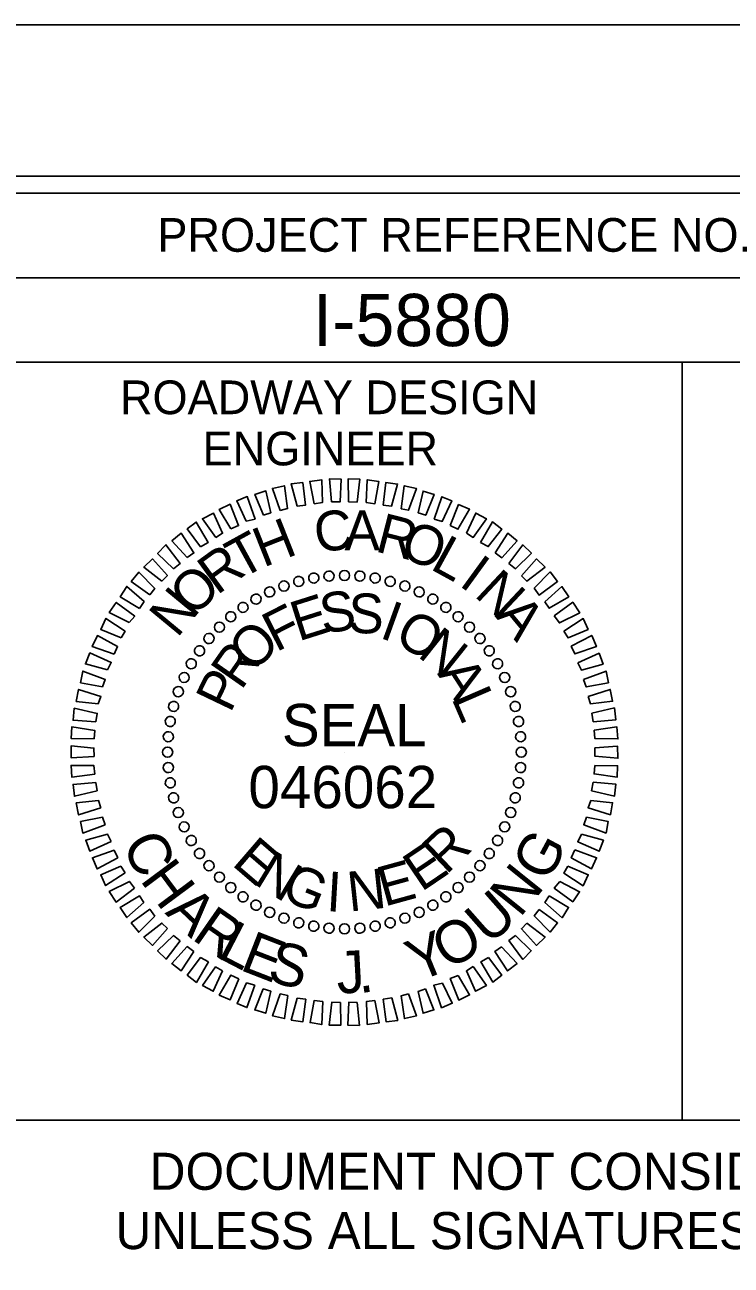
# Model space of a CAD drawing. Extents: x 1648649 to 1651827, y 844691 to 845879.
# Drawn here: x 1651431.8 to 1651536.5, y 845606.9 to 845791 of the extents above; entities that cross this region are included whole.
import ezdxf

# ---------------------------------------------------------------- set-up
doc = ezdxf.new("R2010")
doc.units = 0
for name, color, linetype in [('Default', 7, 'Continuous'), ('Old_Level_2', 7, 'Continuous'), ('Sheet Cutting Line CELL', 7, 'Continuous'), ('Sheet Data Field CELL', 7, 'Continuous'), ('Sheet Plot Border Inside CELL', 7, 'Continuous'), ('Sheet Plot Border Outside CELL', 7, 'Continuous'), ('Sheet Profile CELL', 7, 'Continuous'), ('Sheet Profile Grid Major CELL', 7, 'Continuous'), ('Sheet Profile Grid Minor CELL', 7, 'Continuous'), ('Sheet Sticker Exception Certification CELL', 7, 'Continuous')]:
    doc.layers.add(name, color=color, linetype=linetype)

msp = doc.modelspace()

# ---------------------------------------------------------------- linework, layer by layer
at = {"layer": 'Old_Level_2'}
for p, q in [((1651472.36, 845708.44), (1651472.36, 845708.44)), ((1651474.65, 845708.89), (1651474.65, 845708.89)), ((1651476.9, 845709.25), (1651476.9, 845709.25)), ((1651479.2, 845709.34), (1651479.2, 845709.34)), ((1651481.5, 845709.22), (1651481.5, 845709.22)), ((1651483.75, 845708.9), (1651483.75, 845708.9)), ((1651485.96, 845708.46), (1651485.96, 845708.46)), ((1651468.1, 845706.9), (1651468.1, 845706.9)), ((1651470.18, 845707.77), (1651470.18, 845707.77)), ((1651488.17, 845707.77), (1651488.17, 845707.77)), ((1651490.27, 845706.87), (1651490.27, 845706.87)), ((1651464.11, 845704.58), (1651464.11, 845704.58)), ((1651466.08, 845705.82), (1651466.08, 845705.82)), ((1651492.33, 845705.86), (1651492.33, 845705.86)), ((1651494.24, 845704.58), (1651494.24, 845704.58)), ((1651462.31, 845703.24), (1651462.31, 845703.24)), ((1651496.09, 845703.2), (1651496.09, 845703.2)), ((1651460.61, 845701.64), (1651460.61, 845701.64)), ((1651497.74, 845701.66), (1651497.74, 845701.66)), ((1651459.07, 845699.99), (1651459.07, 845699.99)), ((1651499.34, 845699.96), (1651499.34, 845699.96)), ((1651457.69, 845698.14), (1651457.69, 845698.14)), ((1651500.68, 845698.16), (1651500.68, 845698.16)), ((1651456.42, 845696.23), (1651456.42, 845696.23)), ((1651501.91, 845696.19), (1651501.91, 845696.19)), ((1651455.41, 845694.18), (1651455.41, 845694.18)), ((1651502.99, 845694.17), (1651502.99, 845694.17)), ((1651454.5, 845692.07), (1651454.5, 845692.07)), ((1651503.87, 845692.09), (1651503.87, 845692.09)), ((1651453.81, 845689.86), (1651453.81, 845689.86)), ((1651504.53, 845689.91), (1651504.53, 845689.91)), ((1651453.37, 845687.66), (1651453.37, 845687.66)), ((1651504.99, 845687.62), (1651504.99, 845687.62)), ((1651453.05, 845685.4), (1651453.05, 845685.4)), ((1651505.34, 845685.37), (1651505.34, 845685.37)), ((1651452.93, 845683.1), (1651452.93, 845683.1)), ((1651479.18, 845683.09), (1651479.18, 845683.09)), ((1651505.44, 845683.07), (1651505.44, 845683.07)), ((1651453.02, 845680.8), (1651453.02, 845680.8)), ((1651505.32, 845680.77), (1651505.32, 845680.77)), ((1651453.38, 845678.56), (1651453.38, 845678.56)), ((1651504.99, 845678.52), (1651504.99, 845678.52)), ((1651453.84, 845676.26), (1651453.84, 845676.26)), ((1651504.56, 845676.31), (1651504.56, 845676.31)), ((1651454.5, 845674.08), (1651454.5, 845674.08)), ((1651503.87, 845674.1), (1651503.87, 845674.1)), ((1651455.37, 845672), (1651455.37, 845672)), ((1651502.96, 845672), (1651502.96, 845672)), ((1651456.46, 845669.98), (1651456.46, 845669.98)), ((1651501.95, 845669.94), (1651501.95, 845669.94)), ((1651457.69, 845668.02), (1651457.69, 845668.02)), ((1651500.68, 845668.03), (1651500.68, 845668.03)), ((1651459.03, 845666.21), (1651459.03, 845666.21)), ((1651499.3, 845666.18), (1651499.3, 845666.18)), ((1651460.63, 845664.51), (1651460.63, 845664.51)), ((1651497.76, 845664.53), (1651497.76, 845664.53)), ((1651462.28, 845662.97), (1651462.28, 845662.97)), ((1651496.06, 845662.93), (1651496.06, 845662.93)), ((1651464.13, 845661.59), (1651464.13, 845661.59)), ((1651466.04, 845660.32), (1651466.04, 845660.32)), ((1651492.29, 845660.36), (1651492.29, 845660.36)), ((1651494.25, 845661.59), (1651494.25, 845661.59)), ((1651468.09, 845659.31), (1651468.09, 845659.31)), ((1651490.27, 845659.28), (1651490.27, 845659.28)), ((1651470.2, 845658.4), (1651470.2, 845658.4)), ((1651472.41, 845657.71), (1651472.41, 845657.71)), ((1651474.61, 845657.28), (1651474.61, 845657.28)), ((1651476.87, 845656.95), (1651476.87, 845656.95)), ((1651479.17, 845656.83), (1651479.17, 845656.83)), ((1651481.47, 845656.93), (1651481.47, 845656.93)), ((1651483.71, 845657.28), (1651483.71, 845657.28)), ((1651486.01, 845657.74), (1651486.01, 845657.74)), ((1651488.19, 845658.4), (1651488.19, 845658.4))]:
    msp.add_line(p, q, dxfattribs=at)
for points in [[(1651472.17, 845719.57), (1651471.27, 845722.9), (1651473, 845723.09), (1651473.42, 845719.75)], [(1651474.67, 845719.93), (1651474.04, 845723.26), (1651475.81, 845723.5), (1651475.92, 845720.11)], [(1651477.28, 845720.24), (1651476.96, 845723.63), (1651478.69, 845723.61), (1651478.54, 845720.21)], [(1651479.79, 845720.23), (1651479.73, 845723.63), (1651481.46, 845723.6), (1651481.05, 845720.2)], [(1651482.41, 845720.12), (1651482.56, 845723.52), (1651484.29, 845723.23), (1651483.67, 845719.93)], [(1651484.92, 845719.74), (1651485.34, 845723.1), (1651487.07, 845722.86), (1651486.18, 845719.61)], [(1651467.17, 845718.23), (1651465.91, 845721.34), (1651467.53, 845721.84), (1651468.26, 845718.61)], [(1651469.67, 845718.95), (1651468.51, 845722.23), (1651470.28, 845722.62), (1651470.76, 845719.23)], [(1651487.6, 845719.21), (1651488.06, 845722.62), (1651489.85, 845722.23), (1651488.7, 845718.97)], [(1651490.12, 845718.58), (1651490.85, 845721.83), (1651492.48, 845721.34), (1651491.23, 845718.23)], [(1651462.34, 845716.21), (1651460.62, 845719.11), (1651462.23, 845719.87), (1651463.48, 845716.7)], [(1651464.62, 845717.35), (1651463.21, 845720.36), (1651464.77, 845721.01), (1651465.92, 845717.68)], [(1651492.49, 845717.68), (1651493.64, 845720.99), (1651495.11, 845720.39), (1651493.7, 845717.33)], [(1651494.86, 845716.72), (1651496.11, 845719.83), (1651497.75, 845719.13), (1651496.02, 845716.17)], [(1651460.12, 845714.92), (1651458.13, 845717.71), (1651459.74, 845718.57), (1651461.1, 845715.56)], [(1651497.29, 845715.56), (1651498.65, 845718.57), (1651500.23, 845717.71), (1651498.29, 845714.95)], [(1651455.88, 845711.97), (1651453.59, 845714.44), (1651454.98, 845715.56), (1651456.86, 845712.66)], [(1651457.84, 845713.57), (1651455.86, 845716.2), (1651457.2, 845717.22), (1651458.98, 845714.22)], [(1651499.35, 845714.19), (1651501.13, 845717.25), (1651502.51, 845716.18), (1651500.51, 845713.58)], [(1651501.52, 845712.66), (1651503.41, 845715.57), (1651504.79, 845714.44), (1651502.53, 845711.94)], [(1651453.82, 845710.31), (1651451.48, 845712.57), (1651452.71, 845713.85), (1651454.8, 845711.06)], [(1651503.54, 845711.07), (1651505.63, 845713.83), (1651506.91, 845712.59), (1651504.54, 845710.3)], [(1651452.12, 845708.45), (1651449.42, 845710.55), (1651450.71, 845711.77), (1651452.94, 845709.3)], [(1651505.45, 845709.27), (1651507.66, 845711.77), (1651508.93, 845710.54), (1651506.25, 845708.45)], [(1651450.33, 845706.43), (1651447.57, 845708.42), (1651448.7, 845709.8), (1651451.04, 845707.38)], [(1651507.31, 845707.42), (1651509.68, 845709.82), (1651510.8, 845708.43), (1651508.06, 845706.39)], [(1651448.79, 845704.42), (1651445.94, 845706.14), (1651446.91, 845707.68), (1651449.46, 845705.42)], [(1651508.92, 845705.41), (1651511.44, 845707.65), (1651512.46, 845706.15), (1651509.56, 845704.43)], [(1651447.26, 845702.3), (1651444.31, 845703.81), (1651445.33, 845705.3), (1651448.08, 845703.25)], [(1651510.31, 845703.29), (1651513.05, 845705.33), (1651514.07, 845703.78), (1651511.06, 845702.26)], [(1651446.05, 845700.03), (1651443.04, 845701.28), (1651443.8, 845702.92), (1651446.66, 845701.03)], [(1651511.71, 845701.02), (1651514.61, 845702.9), (1651515.32, 845701.29), (1651512.36, 845700.03)], [(1651445.04, 845697.6), (1651441.78, 845698.75), (1651442.54, 845700.38), (1651445.55, 845698.76)], [(1651512.8, 845698.79), (1651515.86, 845700.41), (1651516.56, 845698.75), (1651513.34, 845697.65)], [(1651444.04, 845695.29), (1651440.78, 845696.17), (1651441.43, 845697.8), (1651444.59, 845696.39)], [(1651513.78, 845696.35), (1651516.95, 845697.76), (1651517.55, 845696.15), (1651514.32, 845695.26)], [(1651443.3, 845692.76), (1651440.04, 845693.39), (1651440.38, 845695.12), (1651443.7, 845693.87)], [(1651514.66, 845693.85), (1651517.99, 845695.11), (1651518.33, 845693.39), (1651515.05, 845692.76)], [(1651442.66, 845690.24), (1651439.41, 845690.6), (1651439.75, 845692.39), (1651443.06, 845691.35)], [(1651515.33, 845691.35), (1651518.61, 845692.4), (1651518.95, 845690.63), (1651515.67, 845690.26)], [(1651442.29, 845687.57), (1651438.94, 845687.82), (1651439.12, 845689.6), (1651442.53, 845688.83)], [(1651515.85, 845688.85), (1651519.23, 845689.64), (1651519.42, 845687.87), (1651516.08, 845687.6)], [(1651442.07, 845685.05), (1651438.67, 845685.1), (1651438.75, 845686.83), (1651442.15, 845686.31)], [(1651516.21, 845686.35), (1651519.6, 845686.82), (1651519.73, 845685.05), (1651516.33, 845685.09)], [(1651442.07, 845682.44), (1651438.67, 845682.22), (1651438.64, 845684), (1651442.04, 845683.69)], [(1651516.3, 845683.73), (1651519.7, 845683.95), (1651519.73, 845682.17), (1651516.33, 845682.48)], [(1651442.16, 845679.83), (1651438.77, 845679.35), (1651438.64, 845681.12), (1651442.04, 845681.08)], [(1651516.3, 845681.12), (1651519.7, 845681.07), (1651519.62, 845679.35), (1651516.21, 845679.86)], [(1651442.52, 845677.32), (1651439.14, 845676.53), (1651438.95, 845678.3), (1651442.29, 845678.57)], [(1651516.08, 845678.61), (1651519.43, 845678.35), (1651519.25, 845676.57), (1651515.84, 845677.35)], [(1651443.04, 845674.82), (1651439.76, 845673.77), (1651439.41, 845675.54), (1651442.7, 845675.91)], [(1651515.71, 845675.93), (1651518.96, 845675.57), (1651518.62, 845673.79), (1651515.31, 845674.83)], [(1651443.71, 845672.32), (1651440.38, 845671.06), (1651440.04, 845672.78), (1651443.32, 845673.41)], [(1651515.07, 845673.41), (1651518.32, 845672.79), (1651517.99, 845671.06), (1651514.67, 845672.31)], [(1651444.59, 845669.83), (1651441.42, 845668.41), (1651440.82, 845670.02), (1651444.04, 845670.92)], [(1651514.33, 845670.89), (1651517.59, 845670), (1651516.94, 845668.37), (1651513.78, 845669.78)], [(1651445.57, 845667.39), (1651442.51, 845665.76), (1651441.8, 845667.42), (1651445.03, 845668.53)], [(1651513.33, 845668.57), (1651516.59, 845667.42), (1651515.83, 845665.79), (1651512.82, 845667.41)], [(1651446.66, 845665.16), (1651443.76, 845663.28), (1651443.05, 845664.88), (1651446.01, 845666.14)], [(1651512.32, 845666.15), (1651515.33, 845664.89), (1651514.57, 845663.26), (1651511.71, 845665.14)], [(1651448.05, 845662.88), (1651445.32, 845660.84), (1651444.3, 845662.4), (1651447.3, 845663.91)], [(1651511.11, 845663.88), (1651514.06, 845662.36), (1651513.04, 845660.88), (1651510.29, 845662.92)], [(1651449.45, 845660.76), (1651446.93, 845658.52), (1651445.91, 845660.02), (1651448.81, 845661.74)], [(1651509.57, 845661.76), (1651512.43, 845660.03), (1651511.46, 845658.5), (1651508.91, 845660.75)], [(1651451.06, 845658.75), (1651448.69, 845656.35), (1651447.57, 845657.75), (1651450.31, 845659.78)], [(1651508.04, 845659.74), (1651510.8, 845657.75), (1651509.67, 845656.37), (1651507.33, 845658.79)], [(1651452.92, 845656.9), (1651450.71, 845654.4), (1651449.44, 845655.63), (1651452.12, 845657.72)], [(1651506.25, 845657.72), (1651508.95, 845655.63), (1651507.66, 845654.4), (1651505.42, 845656.87)], [(1651454.83, 845655.1), (1651452.74, 845652.35), (1651451.46, 845653.58), (1651453.83, 845655.87)], [(1651504.55, 845655.86), (1651506.89, 845653.6), (1651505.66, 845652.33), (1651503.57, 845655.12)], [(1651456.85, 845653.52), (1651454.96, 845650.61), (1651453.58, 845651.73), (1651455.84, 845654.23)], [(1651502.49, 845654.21), (1651504.78, 845651.74), (1651503.39, 845650.61), (1651501.51, 845653.51)], [(1651459.02, 845651.98), (1651457.24, 845648.92), (1651455.86, 845649.99), (1651457.86, 845652.59)], [(1651461.08, 845650.61), (1651459.72, 845647.6), (1651458.14, 845648.46), (1651460.08, 845651.22)], [(1651498.25, 845651.26), (1651500.24, 845648.47), (1651498.63, 845647.6), (1651497.27, 845650.61)], [(1651500.53, 845652.6), (1651502.51, 845649.97), (1651501.17, 845648.95), (1651499.39, 845651.96)], [(1651463.51, 845649.45), (1651462.25, 845646.34), (1651460.62, 845647.04), (1651462.35, 845650)], [(1651496.03, 845649.96), (1651497.75, 845647.06), (1651496.14, 845646.3), (1651494.88, 845649.47)], [(1651465.88, 845648.5), (1651464.73, 845645.18), (1651463.26, 845645.78), (1651464.67, 845648.84)], [(1651468.25, 845647.6), (1651467.52, 845644.34), (1651465.89, 845644.83), (1651467.14, 845647.94)], [(1651491.2, 845647.94), (1651492.46, 845644.83), (1651490.84, 845644.33), (1651490.11, 845647.56)], [(1651493.75, 845648.82), (1651495.16, 845645.82), (1651493.6, 845645.16), (1651492.44, 845648.49)], [(1651470.77, 845646.96), (1651470.3, 845643.55), (1651468.52, 845643.94), (1651469.67, 845647.2)], [(1651473.44, 845646.43), (1651473.03, 845643.08), (1651471.3, 845643.31), (1651472.19, 845646.57)], [(1651475.96, 845646.06), (1651475.81, 845642.65), (1651474.08, 845642.94), (1651474.7, 845646.24)], [(1651478.58, 845645.95), (1651478.64, 845642.55), (1651476.91, 845642.57), (1651477.32, 845645.98)], [(1651481.09, 845645.94), (1651481.41, 845642.54), (1651479.68, 845642.57), (1651479.83, 845645.97)], [(1651483.7, 845646.24), (1651484.33, 845642.91), (1651482.56, 845642.67), (1651482.45, 845646.07)], [(1651486.2, 845646.6), (1651487.1, 845643.27), (1651485.37, 845643.08), (1651484.95, 845646.42)], [(1651488.7, 845647.22), (1651489.86, 845643.95), (1651488.09, 845643.55), (1651487.61, 845646.94)]]:
    msp.add_lwpolyline(points, close=True, dxfattribs=at)
for centre, major_axis in [((1651476.9, 845709.21), (-0.066, 0.75)), ((1651479.18, 845709.31), (0, 0.753)), ((1651481.47, 845709.21), (0.066, 0.75)), ((1651470.21, 845707.73), (-0.258, 0.708)), ((1651472.4, 845708.42), (-0.195, 0.727)), ((1651474.63, 845708.92), (-0.131, 0.742)), ((1651483.74, 845708.92), (0.131, 0.742)), ((1651485.97, 845708.42), (0.195, 0.727)), ((1651488.15, 845707.73), (0.258, 0.708)), ((1651466.07, 845705.8), (-0.376, 0.652)), ((1651468.1, 845706.86), (-0.318, 0.682)), ((1651490.27, 845706.86), (0.318, 0.682)), ((1651492.3, 845705.8), (0.376, 0.652)), ((1651464.14, 845704.57), (-0.432, 0.617)), ((1651494.23, 845704.57), (0.432, 0.617)), ((1651462.33, 845703.18), (-0.484, 0.577)), ((1651496.04, 845703.18), (0.484, 0.577)), ((1651459.09, 845699.95), (-0.577, 0.484)), ((1651460.64, 845701.63), (-0.532, 0.532)), ((1651497.73, 845701.63), (0.532, 0.532)), ((1651499.28, 845699.95), (0.577, 0.484)), ((1651457.7, 845698.13), (-0.617, 0.432)), ((1651500.67, 845698.13), (0.617, 0.432)), ((1651456.47, 845696.2), (-0.652, 0.376)), ((1651501.9, 845696.2), (0.652, 0.376)), ((1651455.41, 845694.17), (-0.682, 0.318)), ((1651502.95, 845694.17), (0.682, 0.318)), ((1651454.54, 845692.06), (-0.708, 0.258)), ((1651503.83, 845692.06), (0.708, 0.258)), ((1651453.85, 845689.87), (-0.727, 0.195)), ((1651504.52, 845689.87), (0.727, 0.195)), ((1651453.36, 845687.64), (-0.742, 0.131)), ((1651505.01, 845687.64), (0.742, 0.131)), ((1651453.06, 845685.37), (-0.75, 0.066)), ((1651505.31, 845685.37), (0.75, 0.066)), ((1651452.96, 845683.09), (-0.753, 0)), ((1651505.41, 845683.09), (0.753, 0)), ((1651453.06, 845680.8), (-0.75, -0.066)), ((1651505.31, 845680.8), (0.75, -0.066)), ((1651453.36, 845678.53), (-0.742, -0.131)), ((1651505.01, 845678.53), (0.742, -0.131)), ((1651453.85, 845676.3), (-0.727, -0.195)), ((1651504.52, 845676.3), (0.727, -0.195)), ((1651454.54, 845674.12), (-0.708, -0.258)), ((1651503.83, 845674.12), (0.708, -0.258)), ((1651455.41, 845672), (-0.682, -0.318)), ((1651502.95, 845672), (0.682, -0.318)), ((1651456.47, 845669.97), (-0.652, -0.376)), ((1651501.9, 845669.97), (0.652, -0.376)), ((1651457.7, 845668.04), (-0.617, -0.432)), ((1651500.67, 845668.04), (0.617, -0.432)), ((1651459.09, 845666.23), (-0.577, -0.484)), ((1651499.28, 845666.23), (0.577, -0.484)), ((1651460.64, 845664.54), (-0.532, -0.532)), ((1651497.73, 845664.54), (0.532, -0.532)), ((1651462.33, 845662.99), (-0.484, -0.577)), ((1651464.14, 845661.6), (-0.432, -0.617)), ((1651494.23, 845661.6), (0.432, -0.617)), ((1651496.04, 845662.99), (0.484, -0.577)), ((1651466.07, 845660.37), (-0.376, -0.652)), ((1651492.3, 845660.37), (0.376, -0.652)), ((1651468.1, 845659.32), (-0.318, -0.682)), ((1651470.21, 845658.44), (-0.258, -0.708)), ((1651472.4, 845657.75), (-0.195, -0.727)), ((1651485.97, 845657.75), (0.195, -0.727)), ((1651488.15, 845658.44), (0.258, -0.708)), ((1651490.27, 845659.32), (0.318, -0.682)), ((1651474.63, 845657.26), (-0.131, -0.742)), ((1651476.9, 845656.96), (-0.066, -0.75)), ((1651479.18, 845656.86), (0, -0.753)), ((1651481.47, 845656.96), (0.066, -0.75)), ((1651483.74, 845657.26), (0.131, -0.742))]:
    msp.add_ellipse(centre, major_axis=major_axis, ratio=0.999708, dxfattribs=at)
at = {"layer": 'Sheet Cutting Line CELL'}
msp.add_line((1651646.28, 845791.02), (1649962.28, 845791.02), dxfattribs=at)
at = {"layer": 'Sheet Plot Border Inside CELL'}
msp.add_lwpolyline([(1649975.28, 844713.47), (1651641.78, 844713.47), (1651641.78, 845768.57), (1649975.28, 845768.57)], close=True, dxfattribs=at)
at = {"layer": 'Sheet Plot Border Outside CELL'}
msp.add_lwpolyline([(1649962.28, 844691.02), (1651646.28, 844691.02), (1651646.28, 845791.02), (1649962.28, 845791.02)], close=True, dxfattribs=at)
at = {"layer": 'Sheet Profile CELL'}
for p, q in [((1651429.23, 845753.47), (1651629.28, 845753.47)), ((1651529.28, 845740.97), (1651529.28, 845628.52))]:
    msp.add_line(p, q, dxfattribs=at)
for points in [[(1651629.28, 845766.02), (1650129.28, 845766.02), (1650129.28, 844716.02), (1651629.28, 844716.02)], [(1651429.23, 845766.02), (1651629.28, 845766.02), (1651629.28, 845740.97), (1651429.23, 845740.97)], [(1651429.23, 845740.97), (1651529.28, 845740.97), (1651529.28, 845628.47), (1651429.23, 845628.47)], [(1651529.28, 845740.97), (1651629.28, 845740.97), (1651629.28, 845628.47), (1651529.28, 845628.47)]]:
    msp.add_lwpolyline(points, close=True, dxfattribs=at)
at = {"layer": 'Sheet Profile Grid Major CELL'}
msp.add_lwpolyline([(1651379.28, 845738.96), (1651379.28, 845266.02), (1651429.28, 845266.02), (1651429.28, 845766.02), (1651455.58, 845766.02)], dxfattribs=at)
at = {"layer": 'Sheet Profile Grid Minor CELL'}
msp.add_lwpolyline([(1651424.28, 845766.02), (1651434.28, 845766.02)], dxfattribs=at)
at = {"layer": 'Sheet Sticker Exception Certification CELL'}
msp.add_line((1651429.23, 845628.47), (1651629.27, 845628.47), dxfattribs=at)
msp.add_line((1651429.23, 845628.47), (1651629.27, 845628.47), dxfattribs=at)

# ---------------------------------------------------------------- texts
at = {"layer": 'Default'}
for s, rotation, p in [('C', 297.1999, (1651446.07, 845669.36)), ('G', 61.7998, (1651509.3, 845663.59)), ('H', 306.6436, (1651448.76, 845664.11)), ('N', 51.2288, (1651505.21, 845658.4)), ('U', 41.4347, (1651500.63, 845654.33)), ('A', 316.4834, (1651452.45, 845659.18)), ('R', 325.1961, (1651456.38, 845655.41)), ('L', 332.5683, (1651460.12, 845652.71)), ('Y', 22.2426, (1651490, 845648.88)), ('O', 30.0413, (1651494.53, 845650.66)), ('E', 338.7525, (1651463.5, 845650.83)), ('S', 345.7591, (1651467.55, 845649.16)), ('J', 3.0321, (1651478.14, 845647.23)), ('.', 8.214, (1651481.39, 845647.28))]:
    msp.add_text(s, height=6.27, rotation=rotation, dxfattribs=at).set_placement(p)
at = {"layer": 'Old_Level_2'}
for s, rotation, p in [('H', 21.6195, (1651467.15, 845710.44)), ('C', 7.2199, (1651475.06, 845712.67)), ('A', 0.0203, (1651479.18, 845713.05)), ('R', 345.6211, (1651483.58, 845712.92)), ('T', 28.8198, (1651463.78, 845708.65)), ('O', 338.4212, (1651487.1, 845712.2)), ('L', 331.2209, (1651491.73, 845710.34)), ('R', 36.0205, (1651460.27, 845706.29)), ('I', 324.0201, (1651496.01, 845707.91)), ('O', 43.2217, (1651456.72, 845702.99)), ('N', 316.8189, (1651498.29, 845706.33)), ('N', 50.4235, (1651454.36, 845699.91)), ('E', 17.6111, (1651472.36, 845699.49)), ('S', 8.2556, (1651475.95, 845700.65)), ('S', 358.9004, (1651479.71, 845700.77)), ('F', 26.967, (1651469.04, 845697.87)), ('I', 340.1896, (1651484.22, 845700.12)), ('A', 309.6172, (1651501.42, 845703.29)), ('O', 330.8335, (1651486.33, 845699.42)), ('O', 45.6812, (1651465.65, 845694.72)), ('N', 321.4766, (1651489.86, 845697.39)), ('R', 55.0397, (1651463.86, 845692.13)), ('P', 64.3989, (1651462.25, 845688.75)), ('A', 302.7603, (1651492.89, 845694.73)), ('L', 293.4009, (1651494.99, 845691.15)), ('R', 43.4814, (1651494.25, 845664.78)), ('E', 319.2769, (1651462.32, 845666.42)), ('E', 34.1241, (1651490.58, 845662.26)), ('N', 328.634, (1651465.51, 845663.65)), ('G', 337.9902, (1651469.52, 845661.37)), ('E', 15.4118, (1651485.08, 845660.13)), ('I', 356.7012, (1651476.41, 845659.5)), ('N', 6.0564, (1651479.91, 845659.41))]:
    msp.add_text(s, height=5.9, rotation=rotation, dxfattribs=at).set_placement(p)
for s, height, p in [('SEAL', 6.273, (1651469.91, 845683.97)), ('046062', 6.275, (1651464.94, 845674.77))]:
    msp.add_text(s, height=height, dxfattribs=at).set_placement(p)
at = {"layer": 'Sheet Data Field CELL'}
msp.add_text('I-5880', height=7.75, dxfattribs=at).set_placement((1651474.49, 845743.34))
at = {"layer": 'Sheet Profile CELL'}
for s, height, p in [('PROJECT REFERENCE NO.', 5.0001, (1651451.44, 845757.34)), ('ROADWAY DESIGN', 5.0001, (1651445.89, 845733.24)), ('ENGINEER', 5, (1651458.14, 845725.64))]:
    msp.add_text(s, height=height, dxfattribs=at).set_placement(p)
at = {"layer": 'Sheet Sticker Exception Certification CELL'}
for s, p in [('DOCUMENT NOT CONSIDERED FINAL', (1651450.3, 845618.13)), ('DOCUMENT NOT CONSIDERED FINAL', (1651450.3, 845618.13)), ('UNLESS ALL SIGNATURES COMPLETED', (1651445.23, 845609.33)), ('UNLESS ALL SIGNATURES COMPLETED', (1651445.23, 845609.33))]:
    msp.add_text(s, height=5.5, dxfattribs=at).set_placement(p)

doc.saveas('drawing.dxf')
